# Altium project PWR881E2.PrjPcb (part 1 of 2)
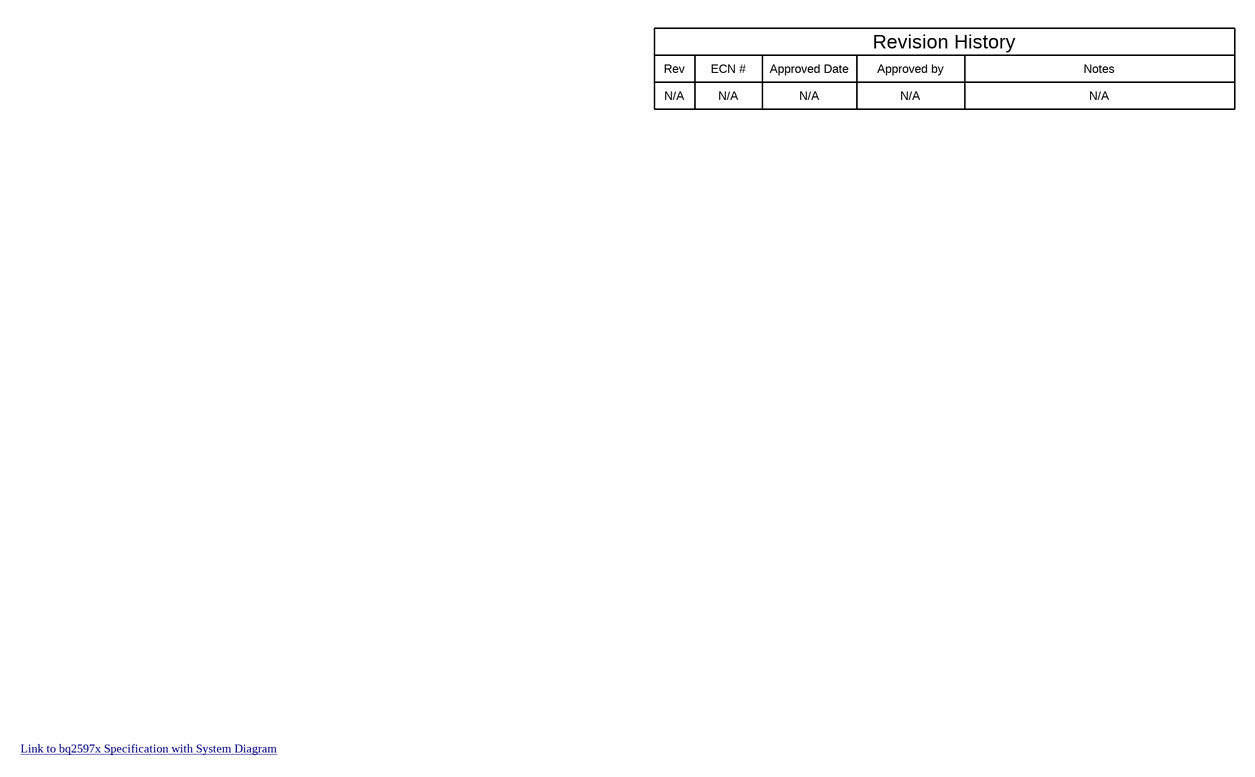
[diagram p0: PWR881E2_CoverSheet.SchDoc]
CopyrightYear: 2017; PCB_Layout: Krypton Solutions/RS; PCB_Rev: E2; PRJ_Customer: Public Release; PRJ_Engineer: Steven Schnier; PRJ_Number: PWR881; PRJ_Title: bq2597x System Evaluation Board; SCH_Rev: E2; TechSupport: http://www.ti.com/support; TID: N/A
4 sheets, 331 parts. Net scope: flat (ports and power ports of the same name join across sheets).
Board file: PWR881E2.PcbDoc
Sheets:
  PWR881E2_CoverSheet.SchDoc
  PWR881E2_MCU_USB.SchDoc
  PWR881E2.SchDoc
  PWR881E2_EVM_Hardware.SchDoc

## Sheet PWR881E2_CoverSheet.SchDoc
size 431 x 279 mm; Date: Not shown in title block; ApprovedBy: Not shown in title block; CheckedBy: Not shown in title block; Author: Not shown in title block; CompanyName: Not shown in title block; Engineer: Not shown in title block; Organization: Not shown in title block; Address1: Not shown in title block; Address2: Not shown in title block; Address3: Not shown in title block; Address4: Not shown in title block; DocumentNumber: 1; Revision: Use project parameter SCH_Rev; SheetNumber: 1; SheetTotal: 4; PageSetup: Record=PageOptions¦CenterHorizontal=True¦CenterVertical=True¦PrintScale=1.00¦XCorrection=1.00¦YCorrection=1.00¦PrintKind=0¦BorderSize=5000000¦LeftOffset=0¦BottomOffset=0¦Orientation=2¦PaperLength=1000¦PaperWidth=1000¦Scale=100¦PaperSource=15¦PrintQuality=600¦MediaType=1¦DitherType=10¦PaperKind=Letter¦PrintScaleMode=1

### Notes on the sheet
- Rev
- N/A
- ECN #
- Approved Date
- Approved by
- Revision History
- Notes
- Link to bq2597x Specification with System Diagram <https://sps09.itg.ti.com/sites/BCP/SCS/projects/bqDoubler>

## Sheet PWR881E2_MCU_USB.SchDoc: MCU and USB
size 431 x 279 mm; Date: Not shown in title block; ApprovedBy: Not shown in title block; CheckedBy: Not shown in title block; Author: Not shown in title block; CompanyName: Not shown in title block; Engineer: Not shown in title block; Organization: Not shown in title block; Address1: Not shown in title block; Address2: Not shown in title block; Address3: Not shown in title block; Address4: Not shown in title block; DocumentNumber: 1; Revision: Use project parameter SCH_Rev; SheetNumber: 2; SheetTotal: 4; PageSetup: Record=PageOptions¦CenterHorizontal=True¦CenterVertical=True¦PrintScale=0.62¦XCorrection=1.00¦YCorrection=1.00¦PrintKind=0¦BorderSize=5000000¦LeftOffset=0¦BottomOffset=0¦Orientation=2¦PaperLength=1000¦PaperWidth=1000¦Scale=100¦PaperSource=15¦PrintQuality=600¦MediaType=1¦DitherType=10¦PrintScaleMode=1¦PaperKind=Letter
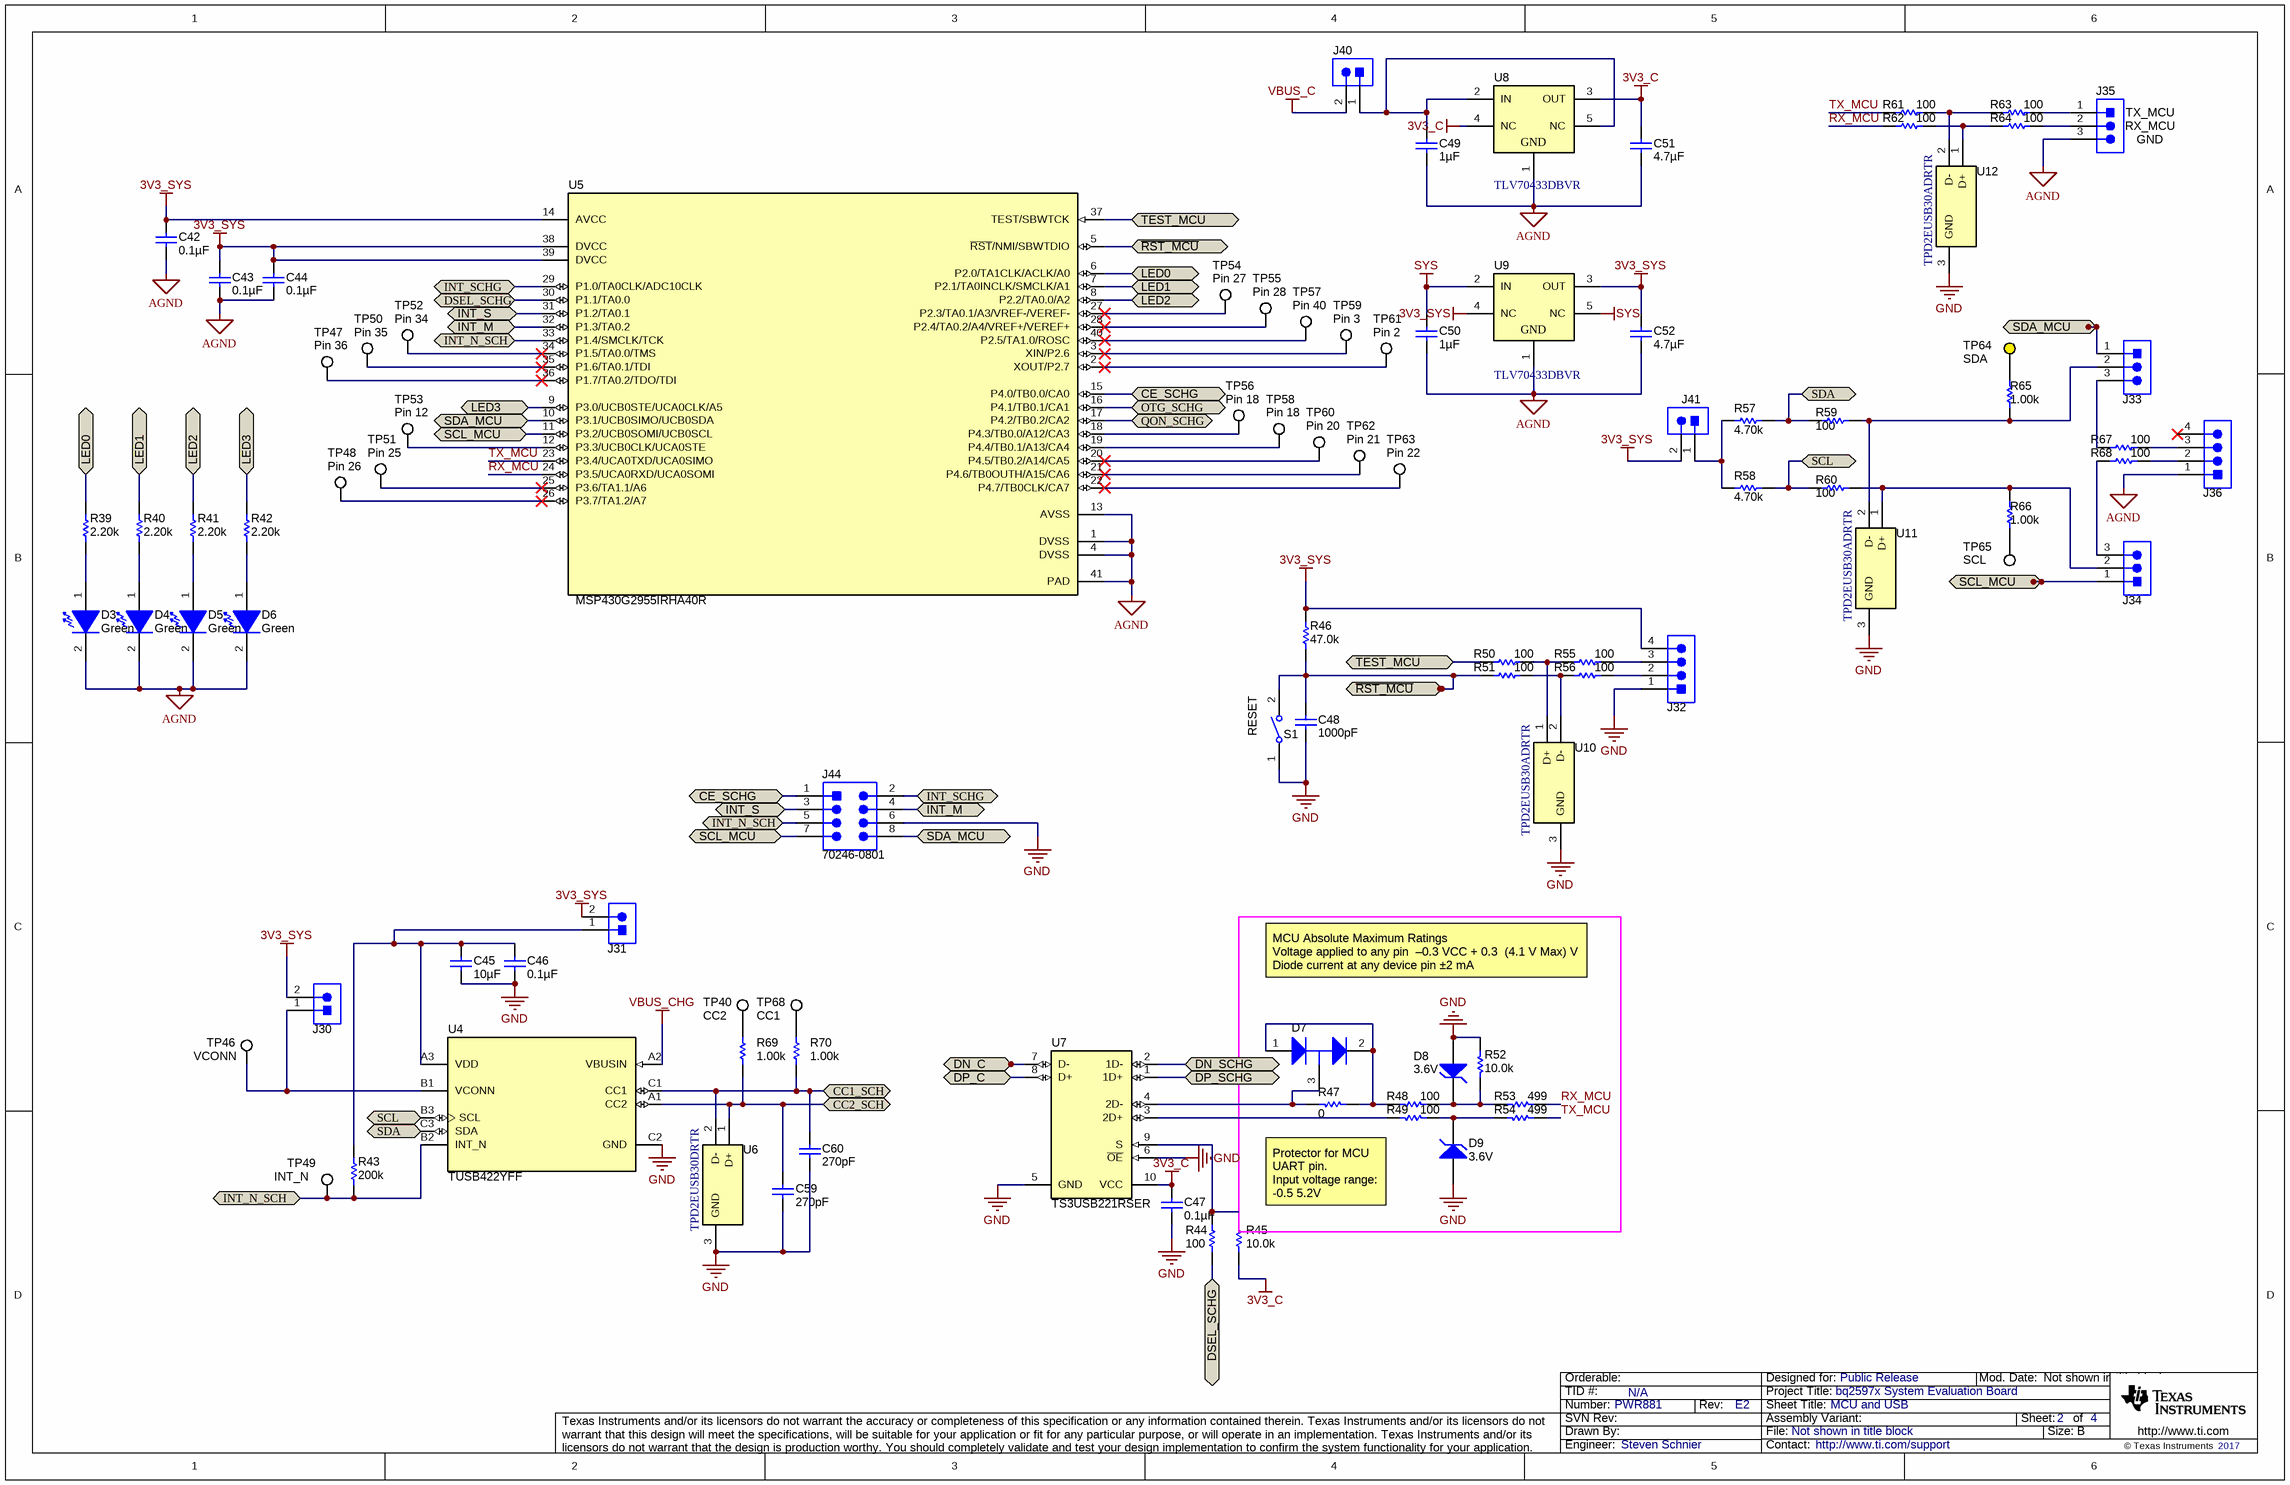
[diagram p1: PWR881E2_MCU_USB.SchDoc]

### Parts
C42  ValueDisplayed: 0.1µF  [0603]  (hidden comment: C1608X7R1E104K080AA)
C43  ValueDisplayed: 0.1µF  [0603_HV]  (hidden comment: C1608X7R1E104K080AA)
C44  ValueDisplayed: 0.1µF  [0603_HV]  (hidden comment: C1608X7R1E104K080AA)
C45  ValueDisplayed: 10µF  [0603]  (hidden comment: GRM188D71A106MA73D)
C46  ValueDisplayed: 0.1µF  [0603]  (hidden comment: C1608X7R1E104K080AA)
C47  ValueDisplayed: 0.1µF  [0603]  (hidden comment: C1608X7R1E104K080AA)
C48  ValueDisplayed: 1000pF  [0603]  (hidden comment: GRM188R71E102KA01D)
C49  ValueDisplayed: 1µF  [0603]  (hidden comment: GRM188R71E105KA12D)
C50  ValueDisplayed: 1µF  [0603]  (hidden comment: GRM188R71E105KA12D)
C51  ValueDisplayed: 4.7µF  [0603]  (hidden comment: GRM188R61C475KAAJ)
C52  ValueDisplayed: 4.7µF  [0603]  (hidden comment: GRM188R61C475KAAJ)
C59  ValueDisplayed: 270pF  [0402L]  (hidden comment: GRM155R71H271KA01D)
C60  ValueDisplayed: 270pF  [0402L]  (hidden comment: GRM155R71H271KA01D)
D3  value Green  [LED_LTST-C190]  (hidden comment: LTST-C190GKT)
D4  value Green  [LED_LTST-C190]  (hidden comment: LTST-C190GKT)
D5  value Green  [LED_LTST-C190]  (hidden comment: LTST-C190GKT)
D6  value Green  [LED_LTST-C190]  (hidden comment: LTST-C190GKT)
D7  BAV99W-7-F  [SOT-323]  (value not drawn)
D8  value 3.6V  [SOD-123]  (hidden comment: MMSZ5227B-7-F)
D9  value 3.6V  [SOD-123]  (hidden comment: MMSZ5227B-7-F)
J30  PEC02SAAN  [CONN_PEC02SAAN]  (value not drawn)
J31  PEC02SAAN  [CONN_PEC02SAAN]  (value not drawn)
J32  22-05-3041  [CONN_22-05-3041]  (value not drawn)
J33  TSW-103-07-T-S  [Samtec_TSW-103-07-T-S]  (value not drawn)
J34  TSW-103-07-T-S  [Samtec_TSW-103-07-T-S]  (value not drawn)
J35  TSW-103-07-T-S  [Samtec_TSW-103-07-T-S]  (value not drawn)
J36  22-05-3041  [CONN_22-05-3041]  (value not drawn)
J40  PEC02SAAN  [CONN_PEC02SAAN]  (value not drawn)
J41  PEC02SAAN  [CONN_PEC02SAAN]  (value not drawn)
J44  70246-0801  [Molex_70246-0801]
R39  ValueDisplayed: 2.20k  [0603L]  (hidden comment: RC0603FR-072K2L)
R40  ValueDisplayed: 2.20k  [0603L]  (hidden comment: RC0603FR-072K2L)
R41  ValueDisplayed: 2.20k  [0603L]  (hidden comment: RC0603FR-072K2L)
R42  ValueDisplayed: 2.20k  [0603L]  (hidden comment: RC0603FR-072K2L)
R43  ValueDisplayed: 200k  [0402]  (hidden comment: CRCW0402200KJNED)
R44  ValueDisplayed: 100  [0603L]  (hidden comment: RC0603FR-07100RL)
R45  ValueDisplayed: 10.0k  [0603L]  (hidden comment: RC0603FR-0710KL)
R46  ValueDisplayed: 47.0k  [0603]  (hidden comment: RC0603FR-0747KL)
R47  ValueDisplayed: 0  [0603]  (hidden comment: RC0603JR-070RL)
R48  ValueDisplayed: 100  [0603]  (hidden comment: RC0603FR-07100RL)
R49  ValueDisplayed: 100  [0603]  (hidden comment: RC0603FR-07100RL)
R50  ValueDisplayed: 100  [0603]  (hidden comment: RC0603FR-07100RL)
R51  ValueDisplayed: 100  [0603]  (hidden comment: RC0603FR-07100RL)
R52  ValueDisplayed: 10.0k  [0603]  (hidden comment: RC0603FR-0710KL)
R53  ValueDisplayed: 499  [0603]  (hidden comment: RT0603DRE07499RL)
R54  ValueDisplayed: 499  [0603]  (hidden comment: RT0603DRE07499RL)
R55  ValueDisplayed: 100  [0603]  (hidden comment: RC0603FR-07100RL)
R56  ValueDisplayed: 100  [0603]  (hidden comment: RC0603FR-07100RL)
R57  ValueDisplayed: 4.70k  [0603]  (hidden comment: RC0603FR-074K7L)
R58  ValueDisplayed: 4.70k  [0603]  (hidden comment: RC0603FR-074K7L)
R59  ValueDisplayed: 100  [0603]  (hidden comment: RC0603FR-07100RL)
R60  ValueDisplayed: 100  [0603]  (hidden comment: RC0603FR-07100RL)
R61  ValueDisplayed: 100  [0603]  (hidden comment: RC0603FR-07100RL)
R62  ValueDisplayed: 100  [0603]  (hidden comment: RC0603FR-07100RL)
R63  ValueDisplayed: 100  [0603]  (hidden comment: RC0603FR-07100RL)
R64  ValueDisplayed: 100  [0603]  (hidden comment: RC0603FR-07100RL)
R65  ValueDisplayed: 1.00k  [0603]  (hidden comment: RC0603FR-071KL)
R66  ValueDisplayed: 1.00k  [0603]  (hidden comment: RC0603FR-071KL)
R67  ValueDisplayed: 100  [0603]  (hidden comment: RC0603FR-07100RL)
R68  ValueDisplayed: 100  [0603]  (hidden comment: RC0603FR-07100RL)
R69  ValueDisplayed: 1.00k  [0603]  (hidden comment: RC0603FR-071KL)
R70  ValueDisplayed: 1.00k  [0603]  (hidden comment: RC0603FR-071KL)
S1  ADTSM31NV  [SW_ADTSM31N]  (value not drawn)
TP40  CC2  [Keystone5012]
TP46  VCONN  [Keystone5012]
TP47  Pin 36  [Keystone5002]
TP48  Pin 26  [Keystone5002]
TP49  INT_N  [Keystone5012]
TP50  Pin 35  [Keystone5002]
TP51  Pin 25  [Keystone5002]
TP52  Pin 34  [Keystone5002]
TP53  Pin 12  [Keystone5002]
TP54  Pin 27  [Keystone5002]
TP55  Pin 28  [Keystone5002]
TP56  Pin 18  [Keystone5002]
TP57  Pin 40  [Keystone5002]
TP58  Pin 18  [Keystone5002]
TP59  Pin 3  [Keystone5002]
TP60  Pin 20  [Keystone5002]
TP61  Pin 2  [Keystone5002]
TP62  Pin 21  [Keystone5002]
TP63  Pin 22  [Keystone5002]
TP64  SDA  [Keystone5004]
TP65  SCL  [Keystone5002]
TP68  CC1  [Keystone5012]
U4  TUSB422YFF  [YFF0009AJAK]
U5  MSP430G2955IRHA40R  [RHA0040B]
U6  TPD2EUSB30DRTR  [DRT0003A]
U7  TS3USB221RSER  [RSE0010A]
U8  TLV70433DBVR  [DBV0005A_N]
U9  TLV70433DBVR  [DBV0005A_N]
U10  TPD2EUSB30ADRTR  [DRT0003A]
U11  TPD2EUSB30ADRTR  [DRT0003A]
U12  TPD2EUSB30ADRTR  [DRT0003A]

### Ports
CC1_SCH (bidir), CC2_SCH (bidir), CE_SCHG (bidir), DN_C (bidir), DN_SCHG (bidir), DP_C (bidir), DP_SCHG (bidir), DSEL_SCHG (bidir), INT_M (bidir), INT_N_SCH (bidir), INT_S (bidir), INT_SCHG (bidir), LED0 (bidir), LED1 (bidir), LED2 (bidir), LED3 (bidir), OTG_SCHG (bidir), QON_SCHG (bidir), SCL (bidir), SCL_MCU (bidir), SDA (bidir), SDA_MCU (bidir), TEST_MCU (bidir), ~{RST_MCU} (bidir)

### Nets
3V3_C: C47.2 C51.1 R45.1 U7.10(VCC) U8.3(OUT) U8.4(NC)
3V3_SYS: C42.1 C43.1 C44.1 C52.1 J30.2 J31.2 J32.4 J41.2 R46.2 U5.14(AVCC) U5.38(DVCC) U5.39(DVCC) U9.3(OUT) U9.4(NC)
AGND: C42.2 C43.2 C44.2 C49.2 C50.2 C51.2 C52.2 D3.2(K) D4.2(K) D5.2(K) D6.2(K) J35.3 J36.1 U5.1(DVSS) U5.4(DVSS) U5.13(AVSS) U5.41(PAD) U8.1(GND) U9.1(GND)
GND: C45.2 C46.2 C47.1 C48.2 C59.2 C60.2 D8.2(A) D9.2(A) J32.1 J44.6 R52.1 S1.1 U4.C2(GND) U6.3(GND) U7.5(GND) U7.6(~{OE}) U10.3(GND) U11.3(GND) U12.3(GND)
SYS: C50.1 U9.2(IN) U9.5(NC)
VBUS_C: J40.2
VBUS_CHG: U4.A2(VBUSIN)
~{RST_MCU}: C48.1 R46.1 R51.1 S1.2 U5.5(~{RST}/NMI/SBWTDIO) ; port ~{RST_MCU}
CC1_SCH: C60.1 R70.2 U4.C1(CC1) U6.2(D-) ; port CC1_SCH
CC2_SCH: C59.1 R69.2 U4.A1(CC2) U6.1(D+) ; port CC2_SCH
CE_SCHG: J44.1 U5.15(P4.0/TB0.0/CA0) ; port CE_SCHG
DN_C: U7.7(D-) ; port DN_C
DN_SCHG: U7.2(1D-) ; port DN_SCHG
DP_C: U7.8(D+) ; port DP_C
DP_SCHG: U7.1(1D+) ; port DP_SCHG
DSEL_SCHG: R44.2 U5.30(P1.1/TA0.0) ; port DSEL_SCHG
INT_M: J44.4 U5.32(P1.3/TA0.2) ; port INT_M
INT_N_SCH: J44.5 R43.1 TP49.1 U4.B2(INT_N) U5.33(P1.4/SMCLK/TCK) ; port INT_N_SCH
INT_S: J44.3 U5.31(P1.2/TA0.1) ; port INT_S
INT_SCHG: J44.2 U5.29(P1.0/TA0CLK/ADC10CLK) ; port INT_SCHG
LED0: R39.2 U5.6(P2.0/TA1CLK/ACLK/A0) ; port LED0
LED1: R40.2 U5.7(P2.1/TA0INCLK/SMCLK/A1) ; port LED1
LED2: R41.2 U5.8(P2.2/TA0.0/A2) ; port LED2
LED3: R42.2 U5.9(P3.0/UCB0STE/UCA0CLK/A5) ; port LED3
OTG_SCHG: U5.16(P4.1/TB0.1/CA1) ; port OTG_SCHG
QON_SCHG: U5.17(P4.2/TB0.2/CA2) ; port QON_SCHG
RX_MCU: R53.2 R62.1 U5.24(P3.5/UCA0RXD/UCA0SOMI)
SCL: R58.2 R60.1 U4.B3(SCL) ; port SCL
SCL_MCU: J34.1 J44.7 U5.11(P3.2/UCB0SOMI/UCB0SCL) ; port SCL_MCU
SDA: R57.2 R59.1 U4.C3(SDA) ; port SDA
SDA_MCU: J33.1 J44.8 U5.10(P3.1/UCB0SIMO/UCB0SDA) ; port SDA_MCU
TEST_MCU: R50.1 U5.37(TEST/SBWTCK) ; port TEST_MCU
TX_MCU: R54.2 R61.1 U5.23(P3.4/UCA0TXD/UCA0SIMO)
NetC45_1: C45.1 C46.1 J31.1 R43.2 U4.A3(VDD)
NetC49_1: C49.1 J40.1 U8.2(IN) U8.5(NC)
NetD3_1: D3.1(A) R39.1
NetD4_1: D4.1(A) R40.1
NetD5_1: D5.1(A) R41.1
NetD6_1: D6.1(A) R42.1
NetD7_1: D7.1(A) D7.2(K) R47.2 R48.1
NetD7_3: D7.3(C) R47.1 U7.4(2D-)
NetD8_1: D8.1(K) R48.2 R52.2 R53.1
NetD9_1: D9.1(K) R49.2 R54.1
NetJ30_1: J30.1 TP46.1 U4.B1(VCONN)
NetJ32_2: J32.2 R56.2
NetJ32_3: J32.3 R55.2
NetJ33_2: J33.2 R59.2 R65.1 U11.2(D-)
NetJ33_3: J33.3 R67.1
NetJ34_2: J34.2 R60.2 R66.1 U11.1(D+)
NetJ34_3: J34.3 R68.1
NetJ35_1: J35.1 R63.2
NetJ35_2: J35.2 R64.2
NetJ36_2: J36.2 R68.2
NetJ36_3: J36.3 R67.2
NetJ41_1: J41.1 R57.1 R58.1
NetR44_1: R44.1 R45.2 U7.9(S)
NetR49_1: R49.1 U7.3(2D+)
NetR50_2: R50.2 R55.1 U10.1(D+)
NetR51_2: R51.2 R56.1 U10.2(D-)
NetR61_2: R61.2 R63.1 U12.2(D-)
NetR62_2: R62.2 R64.1 U12.1(D+)
NetR65_2: R65.2 TP64.1
NetR66_2: R66.2 TP65.1
NetR69_1: R69.1 TP40.1
NetR70_1: R70.1 TP68.1
NetTP47_1: TP47.1 U5.36(P1.7/TA0.2/TDO/TDI)
NetTP48_1: TP48.1 U5.26(P3.7/TA1.2/A7)
NetTP50_1: TP50.1 U5.35(P1.6/TA0.1/TDI)
NetTP51_1: TP51.1 U5.25(P3.6/TA1.1/A6)
NetTP52_1: TP52.1 U5.34(P1.5/TA0.0/TMS)
NetTP53_1: TP53.1 U5.12(P3.3/UCB0CLK/UCA0STE)
NetTP54_1: TP54.1 U5.27(P2.3/TA0.1/A3/VREF-/VEREF-)
NetTP55_1: TP55.1 U5.28(P2.4/TA0.2/A4/VREF+/VEREF+)
NetTP56_1: TP56.1 U5.18(P4.3/TB0.0/A12/CA3)
NetTP57_1: TP57.1 U5.40(P2.5/TA1.0/ROSC)
NetTP58_1: TP58.1 U5.19(P4.4/TB0.1/A13/CA4)
NetTP59_1: TP59.1 U5.3(XIN/P2.6)
NetTP60_1: TP60.1 U5.20(P4.5/TB0.2/A14/CA5)
NetTP61_1: TP61.1 U5.2(XOUT/P2.7)
NetTP62_1: TP62.1 U5.21(P4.6/TB0OUTH/A15/CA6)
NetTP63_1: TP63.1 U5.22(P4.7/TB0CLK/CA7)

Not connected (* = marked no-connect by the designer): J36 4*

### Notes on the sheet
- (near J35) TX_MCU
- (near J35) RX_MCU
- (near J35) GND
- (near S1) RESET
- MCU Absolute Maximum Ratings
  Voltage applied to any pin  –0.3 VCC + 0.3  (4.1 V Max) V
  Diode current at any device pin ±2 mA
- Protector for MCU UART pin.
  Input voltage range: -0.5 5.2V

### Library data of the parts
C42 C46 C47 = C1608X7R1E104K080AA: CAP, CERM, 0.1 µF, 25 V, +/- 10%, X7R, 0603; Manufacturer: TDK; Polarized: N; CompType: Capacitor; Value: 0.1uF; U/M: EA; Cap_F: 0.0000001; Tolerance_%: 10; Value1: Unknown; VDC_V: 25; Value2: 25V; TaMin_C: -55; TaMax_C: 125; SizeArea_mm2: 1.28; SizeAreaWB_mm2: 4.68; SizeX_mm: 1.6; SizeY_mm: 0.8; SizeZ_mm: 1; AEC Category: Q200
C43 C44 = C1608X7R1E104K080AA: CAP, CERM, 0.1 µF, 25 V, +/- 10%, X7R, 0603; Manufacturer: TDK; Polarized: N; CompType: Capacitor; Value: 0.1uF; U/M: EA; Cap_F: 0.0000001; Tolerance_%: 10; Value1: Unknown; VDC_V: 25; Value2: 25V; TaMin_C: -55; TaMax_C: 125; Cap_Case: 0603; SizeArea_mm2: 1.28; SizeAreaWB_mm2: 4.68; SizeX_mm: 1.6; SizeY_mm: 0.8; SizeZ_mm: 1; AEC Category: Q200
C45 = GRM188D71A106MA73D: CAP, CERM, 10 µF, 10 V, +/- 20%, X7T, 0603; Manufacturer: MuRata; Polarized: N; CompType: Capacitor; Value: 10uF; U/M: EA; Cap_F: 0.00001; Tolerance_%: 20; Value1: Unknown; VDC_V: 10; Value2: 10V; TaMin_C: -55; TaMax_C: 125; SizeArea_mm2: 1.28; SizeAreaWB_mm2: 4.68; SizeX_mm: 1.6; SizeY_mm: 0.8; SizeZ_mm: 1; AEC Category: Q200
C48 = GRM188R71E102KA01D: CAP, CERM, 1000 pF, 25 V, +/- 10%, X7R, 0603; Manufacturer: MuRata; Polarized: N; CompType: Capacitor; Value: 1000pF; U/M: EA; Cap_F: 0.000000001; Tolerance_%: 10; Value1: Unknown; VDC_V: 25; Value2: 25V; TaMin_C: -55; TaMax_C: 125; SizeArea_mm2: 1.28; SizeAreaWB_mm2: 4.68; SizeX_mm: 1.6; SizeY_mm: 0.8; SizeZ_mm: 1; AEC Category: Q200
C49 C50 = GRM188R71E105KA12D: CAP, CERM, 1 µF, 25 V, +/- 10%, X7R, 0603; Manufacturer: MuRata; Polarized: N; CompType: Capacitor; Value: 1uF; U/M: EA; Cap_F: 0.000001; Tolerance_%: 10; Value1: Unknown; VDC_V: 25; Value2: 25V; TaMin_C: -55; TaMax_C: 125; AEC Category: Q200; SizeArea_mm2: 1.28; SizeAreaWB_mm2: 4.68; SizeX_mm: 1.6; SizeY_mm: 0.8; SizeZ_mm: 1
C51 C52 = GRM188R61C475KAAJ: CAP, CERM, 4.7 µF, 16 V, +/- 10%, X5R, 0603; Manufacturer: MuRata; Polarized: N; CompType: Capacitor; Value: 4.7uF; U/M: EA; Cap_F: 0.0000047; Tolerance_%: 10; Value1: Unknown; VDC_V: 16; Value2: 16V; TaMin_C: -55; TaMax_C: 85; AEC Category: Q200; SizeArea_mm2: 1.28; SizeAreaWB_mm2: 4.68; SizeX_mm: 1.6; SizeY_mm: 0.8; SizeZ_mm: 1
C59 C60 = GRM155R71H271KA01D: CAP, CERM, 270 pF, 50 V,+/- 10%, X7R, 0402; Manufacturer: MuRata; Polarized: N; CompType: Capacitor; Value: 270pF; U/M: EA; Cap_F: 0.00000000027; Tolerance_%: 10; VDC_V: 50; Value2: 50V; TaMin_C: -55; TaMax_C: 125; Cap_Case: 0402; SizeArea_mm2: 0.5; SizeAreaWB_mm2: 3; SizeX_mm: 1; SizeZ_mm: 0.6; AEC Category: Q200
D3-D6 = LTST-C190GKT: LED, Green, SMD; Manufacturer: Lite-On; Vf_V: 2.1; Value2: 2.1V; Io_A: 0.02; Power_TotalModule: 0.1; Value1: 0.1W; U/M: EA
D7 = BAV99W-7-F: Diode, Switching, 75 V, 0.15 A, SOT-323; Manufacturer: Diodes Inc.; U/M: EA; Vf_V: 1.25; Value: 75V; Value1: 0.15A; Value2: 1.25V; Io_A: 0.15; Vr_V: 75; TJmax_C: 150; AEC Category: Q101; SizeAreaWB_mm2: 10.24; SizeArea_mm2: 4.84; SizeX_mm: 2.2; SizeZ_mm: 1.1
D8 D9 = MMSZ5227B-7-F: Diode, Zener, 3.6 V, 500 mW, SOD-123; Manufacturer: Diodes Inc.; SymbolCreator: a0412235; U/M: EA; Power_W: 0.5; Vz_V: 3.6; Value1: 0.5W; RJA_CperW: 350; AEC Category: Q101; SizeAreaWB_mm2: 13.095; SizeArea_mm2: 6.545; SizeX_mm: 3.85; SizeY_mm: 1.7; SizeZ_mm: 1.35
J30 J31 J40 J41 = PEC02SAAN: Header, 100mil, 2x1, Tin, TH; Manufacturer: Sullins Connector Solutions; SymbolCreator: a0412235; Pitch_mm: 2.54; Gender: Male; Shrouded: N; Row_Count: 1; Current_A: 3; Voltage_V: 1800; Cert_UL: Y
J32 J36 = 22-05-3041: Header (friction lock), 100mil, 4x1, R/A, TH; Manufacturer: Molex; SymbolCreator: a0412235
J33-J35 = TSW-103-07-T-S: Header, 2.54 mm, 3x1, Tin, TH; Manufacturer: Samtec; SymbolCreator: a0799628; Pitch_mm: 2.54; Gender: Male; Shrouded: N; Row_Count: 1; Current_A: 6.3; Voltage_V: 550; Cert_CSA: Y
J44 = 70246-0801: Header(shrouded), 2.54mm, 4x2, Gold, TH; Manufacturer: Molex; SymbolCreator: a0411947; Pitch_mm: 2.54; Gender: Male; Shrouded: Y; Row_Count: 2; Current_A: 2.5; Voltage_V: 250
R39-R42 = RC0603FR-072K2L: RES, 2.20 k, 1%, 0.1 W, 0603; Manufacturer: Yageo America; CompType: Resistor; Value: 2.20k; Res_ohm: 2200; Value_Code: 2k20; Tolerance_%: 1; Power_W: 0.1; Value2: 0.1W; VDC_V: 150; TempCo: 200 ppm/C; U/M: EA; AEC Category: Q200; SizeArea_mm2: 1.28; SizeX_mm: 1.6; SizeY_mm: 0.8
R43 = CRCW0402200KJNED: RES, 200 k, 5%, 0.063 W, 0402; Manufacturer: Vishay-Dale; CompType: Resistor; Value: 200k; Res_ohm: 200000; Tolerance_%: 5; Power_W: 0.063; Value2: 0.063W; VDC_V: 50; TempCo: 200 ppm/C; SizeArea_mm2: 0.5; SizeX_mm: 1; SizeZ_mm: 0.6; EIA_Code: E24; U/M: EA; AEC Category: Q200
R44 R48-R51 R55 R56 R59-R64 R67 R68 = RC0603FR-07100RL: RES, 100, 1%, 0.1 W, 0603; Manufacturer: Yageo America; CompType: Resistor; Value: 100; Value_Code: 100R; Tolerance_%: 1; Power_W: 0.1; Value2: 0.1W; VDC_V: 150; TempCo: 200 ppm/C; EIA_Code: E96; U/M: EA; AEC Category: Q200; SizeArea_mm2: 1.28; SizeX_mm: 1.6; SizeY_mm: 0.8
R45 R52 = RC0603FR-0710KL: RES, 10.0 k, 1%, 0.1 W, 0603; Manufacturer: Yageo America; CompType: Resistor; Value: 10.0k; Res_ohm: 10000; Value_Code: 10k0; Tolerance_%: 1; Power_W: 0.1; Value2: 0.1W; VDC_V: 150; TempCo: 200 ppm/C; EIA_Code: E96; U/M: EA; AEC Category: Q200; SizeArea_mm2: 1.28; SizeX_mm: 1.6; SizeY_mm: 0.8
R46 = RC0603FR-0747KL: RES, 47.0 k, 1%, 0.1 W, 0603; Manufacturer: Yageo America; CompType: Resistor; Value: 47.0k; Res_ohm: 47000; Value_Code: 47k0; Tolerance_%: 1; Power_W: 0.1; Value2: 0.1W; VDC_V: 150; TempCo: 200 ppm/C; U/M: EA; AEC Category: Q200; SizeArea_mm2: 1.28; SizeX_mm: 1.6; SizeY_mm: 0.8
R47 = RC0603JR-070RL: RES, 0, 5%, 0.1 W, 0603; Manufacturer: Yageo America; CompType: Resistor; Value: 0; Value_Code: 0000; Tolerance_%: 5; Power_W: 0.1; Value2: 0.1W; VDC_V: 50; TempCo: 200 ppm/C; EIA_Code: E24; U/M: EA; AEC Category: Q200; SizeArea_mm2: 1.28; SizeX_mm: 1.6; SizeY_mm: 0.8; SizeZ_mm: 1
R53 R54 = RT0603DRE07499RL: RES, 499, 0.5%, 0.1 W, 0603; Manufacturer: Yageo America; CompType: Resistor; Value: 499; Value_Code: 499R; Tolerance_%: 0.5; Power_W: 0.1; Value2: 0.1W; VDC_V: 75; TempCo: 50 ppm/C; EIA_Code: E192; U/M: EA; AEC Category: Q200; SizeArea_mm2: 1.28; SizeX_mm: 1.6; SizeY_mm: 0.8; SizeZ_mm: 1
R57 R58 = RC0603FR-074K7L: RES, 4.70 k, 1%, 0.1 W, 0603; Manufacturer: Yageo America; CompType: Resistor; Value: 4.70k; Res_ohm: 4700; Value_Code: 4k70; Tolerance_%: 1; Power_W: 0.1; Value2: 0.1W; VDC_V: 150; TempCo: 200 ppm/C; U/M: EA; AEC Category: Q200; SizeArea_mm2: 1.28; SizeX_mm: 1.6; SizeY_mm: 0.8
R65 R66 R69 R70 = RC0603FR-071KL: RES, 1.00 k, 1%, 0.1 W, 0603; Manufacturer: Yageo America; CompType: Resistor; Value: 1.00k; Res_ohm: 1000; Value_Code: 1k00; Tolerance_%: 1; Power_W: 0.1; Value2: 0.1W; VDC_V: 150; TempCo: 200 ppm/C; EIA_Code: E96; U/M: EA; AEC Category: Q200; SizeArea_mm2: 1.28; SizeX_mm: 1.6; SizeY_mm: 0.8
S1 = ADTSM31NV: Switch, SPST-NO, Off-Mom, 0.05 A, 12 V, SMT; Manufacturer: APEM; SymbolCreator: a0799628; VDC_V: 12; PositionCount: 1; CurrentRating_mA: 50
TP40 TP46 TP49 TP68 = 5012: Test Point, Multipurpose, White, TH; Manufacturer: Keystone; CompType: Test Point Loop; ContactFinish: Silver
TP47 TP48 TP50-TP63 TP65 = 5002: Test Point, Miniature, White, TH; Manufacturer: Keystone; CompType: Test Point Loop; ContactFinish: Silver
TP64 = 5004: Test Point, Miniature, Yellow, TH; Manufacturer: Keystone; CompType: Test Point Loop; ContactFinish: Silver
U4 = TUSB422YFF: USB Type-C Port Control with Power Delivery, YFF0009AJAK (DSBGA-9); Manufacturer: Texas Instruments; SymbolCreator: Altium; SizeArea_mm2: 1.8699; SizeAreaWB_mm2: 5.6049; SizeX_mm: 1.355; SizeY_mm: 1.38; SizeZ_mm: 0.625; CompType: IC; U/M: EA
U5 = MSP430G2955IRHA40R: MIXED SIGNAL MICROCONTROLLER, RHA0040B (VQFN-40); Alternate PartNumber: MSP430G2955IRHA40T; Manufacturer: Texas Instruments; SymbolCreator: Altium; CompType: IC; U/M: EA; SizeArea_mm2: 37.8225; SizeAreaWB_mm2: 66.4225; SizeX_mm: 6.15; SizeZ_mm: 1
U6 = TPD2EUSB30DRTR: ESD Solution for Super-Speed (6 Gbps) USB 3.0 Interface, 2 Channels, -40 to +85 degC, 3-pin SOT (DRT), Green (Rohs & No Sb/Br); Manufacturer: Texas Instruments; Alternate PartNumber: Equivalent; 1394 / Firewire: TRUE; Breakdown Voltage(Min)(V): 9; Differential Capacitance(pF): 0.01; IEC 61000-4-2 Air-Gap(+/- kV): 8; IO Capacitance(Typ)(pF): 0.7; IO Leakage Current(nA): 10
U7 = TS3USB221RSER: High-Speed USB 2.0 (480 Mbps) 1:2 Multiplexer / Demultiplexer Switch with Single Enable, 6 ohm RON, 2.5 to 3.3V, -40 to 85 degC, 10-Pin UQFN (RSE), Green (RoHS & no Sb/Br); Manufacturer: Texas Instruments; Alternate PartNumber: Equivalent; SubFamily: USB Switch; Number of Channels: 2; Architecture: 1; ESD HBM(kV): +/-2; ICC(uA): 30; OFF Time(Max)(ns): 12; Vcc range(V): 2.3 to 3.6; tpd max(ns): 0.25; ron(max)(ohms): 6; RON Mis-match(Max)(Ohms): 0.2; Bandwidth(MHz): 1200
U8 U9 = TLV70433DBVR: Single Output LDO, 150 mA, Fixed 3.3 V Output, 2.5 to 24 V Input, with Ultra-Low IQ, 5-pin SOT-23 (DBV), -40 to 125 degC, Green (RoHS & no Sb/Br); Manufacturer: Texas Instruments; Alternate PartNumber: Equivalent; Accuracy(%): 2; Fixed Output Options(V): 3.3; Iout(Max)(A): 0.15; Iq(Typ)(mA): 0.003; SubFamily: Single Channel LDO; Vdo(Typ)(mV): 400; Vin(Max)(V): 24; Vin(Min)(V): 2.5
U10-U12 = TPD2EUSB30ADRTR: ESD / Surge Solution for High Speed, Low Voltage Interface, 2 Channels, -40 to +85 degC, 3-pin SOT (DRT), Green (RoHS & no Sb/Br); Manufacturer: Texas Instruments; Alternate PartNumber: Equivalent; 1394 / Firewire: TRUE; Breakdown Voltage(Min)(V): 4.5; Differential Capacitance(pF): 0.05; IEC 61000-4-2 Air-Gap(+/- kV): 8; IO Capacitance(Typ)(pF): 0.7; IO Leakage Current(nA): 10; SubFamily: ESD Solution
